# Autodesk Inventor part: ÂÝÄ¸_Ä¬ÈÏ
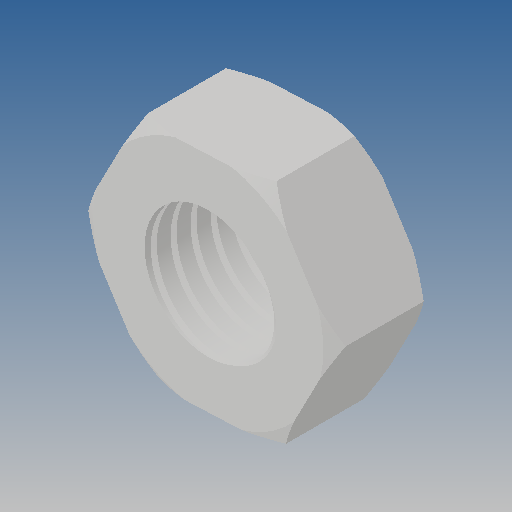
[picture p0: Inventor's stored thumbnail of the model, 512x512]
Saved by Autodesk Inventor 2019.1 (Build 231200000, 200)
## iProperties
Created: 2012-10
Part Number: ÂÝÄ¸_Ä¬ÈÏ
Material: Ogólny
Document SubType Name: Modeling
Designer: CADENGINEERING4
Density: 1 g/cm^3
Appearance: Domyślna
Author: CADENGINEERING4
Revision Number: ÈÎºÎ
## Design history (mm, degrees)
feature "NONE"
node "Bryła1"
